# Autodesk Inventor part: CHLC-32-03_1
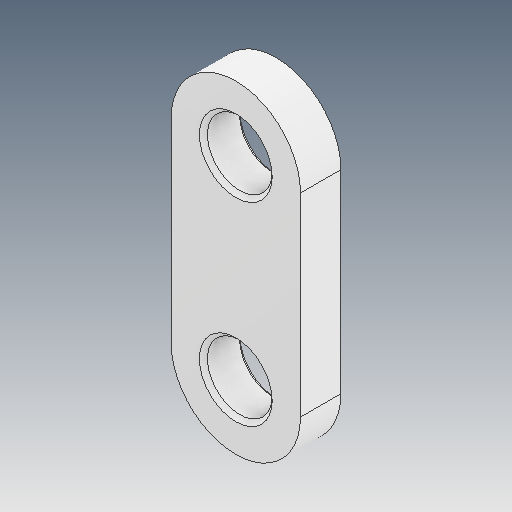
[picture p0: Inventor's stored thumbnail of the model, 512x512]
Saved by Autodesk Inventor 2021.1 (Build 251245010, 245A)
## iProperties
Created: 2021-05
Part Number: CHLC-32-03_1
Material: Ogólny
Document SubType Name: Modeling
Designer: user
Density: 1 g/cm^3
Appearance: Domyślna
Author: user
Revision Number: ÈÎºÎ
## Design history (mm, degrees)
feature "ÊäÈë1"
node "Bryła1"
